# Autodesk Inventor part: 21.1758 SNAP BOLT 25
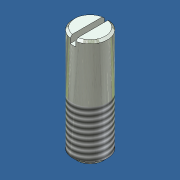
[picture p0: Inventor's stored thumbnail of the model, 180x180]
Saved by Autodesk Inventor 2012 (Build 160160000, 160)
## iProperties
Created: 2007-03
Part Number: 21.1758 SNAP BOLT 25
Document SubType Name: Modeling
Designer: Andy Moles
Material: Steel
Mass: 9.62317 g
Surface Area: 7.26478 cm^2
Volume: 1.22588 cm^3
Density: 7.85 g/cm^3
Author: Andy Moles
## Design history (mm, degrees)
sketch "Sketch1"
  geometry: C1 r 4 at (0, 0); 1 further point
  constraints: 1 centre point, 1 coincident
  dimensions: "d0" = 8 diameter of C1
extrude "Extrusion1" new body sketch "Sketch1" distance "d1" = 25; taper "d2" = 0 deg
thread "Thread1" dims "d3" = 12, "d4" = 0
chamfer "Chamfer1" distance "d5" = 1; stored, may be unused: second distance "d6" = 2, angle "d7" = 45 deg
sketch "Sketch2"
  geometry: L1 (-0.65, 3.947)-(-0.65, -3.947); L2 (0.65, 3.947)-(0.65, -3.947); A1 r 4 centre (0, 0) between (-0.65, 3.947) and (-0.65, -3.947) reference
  constraints: 4 end point, 4 point on circle, 1 parallel, 1 vertical
  dimensions: "d8" = 1.3 distance between parallel lines of L2 L1; "d9" = 0.65 distance from line of A1.centre L1 (= 0.5 x d8)
extrude "Extrusion2" cut sketch "Sketch2" distance "d10" = 1.6; taper "d11" = 0 deg
chamfer "Chamfer2" distance "d12" = 0.5; stored, may be unused: second distance "d13" = 2, angle "d14" = 45 deg
body "Solid1"
